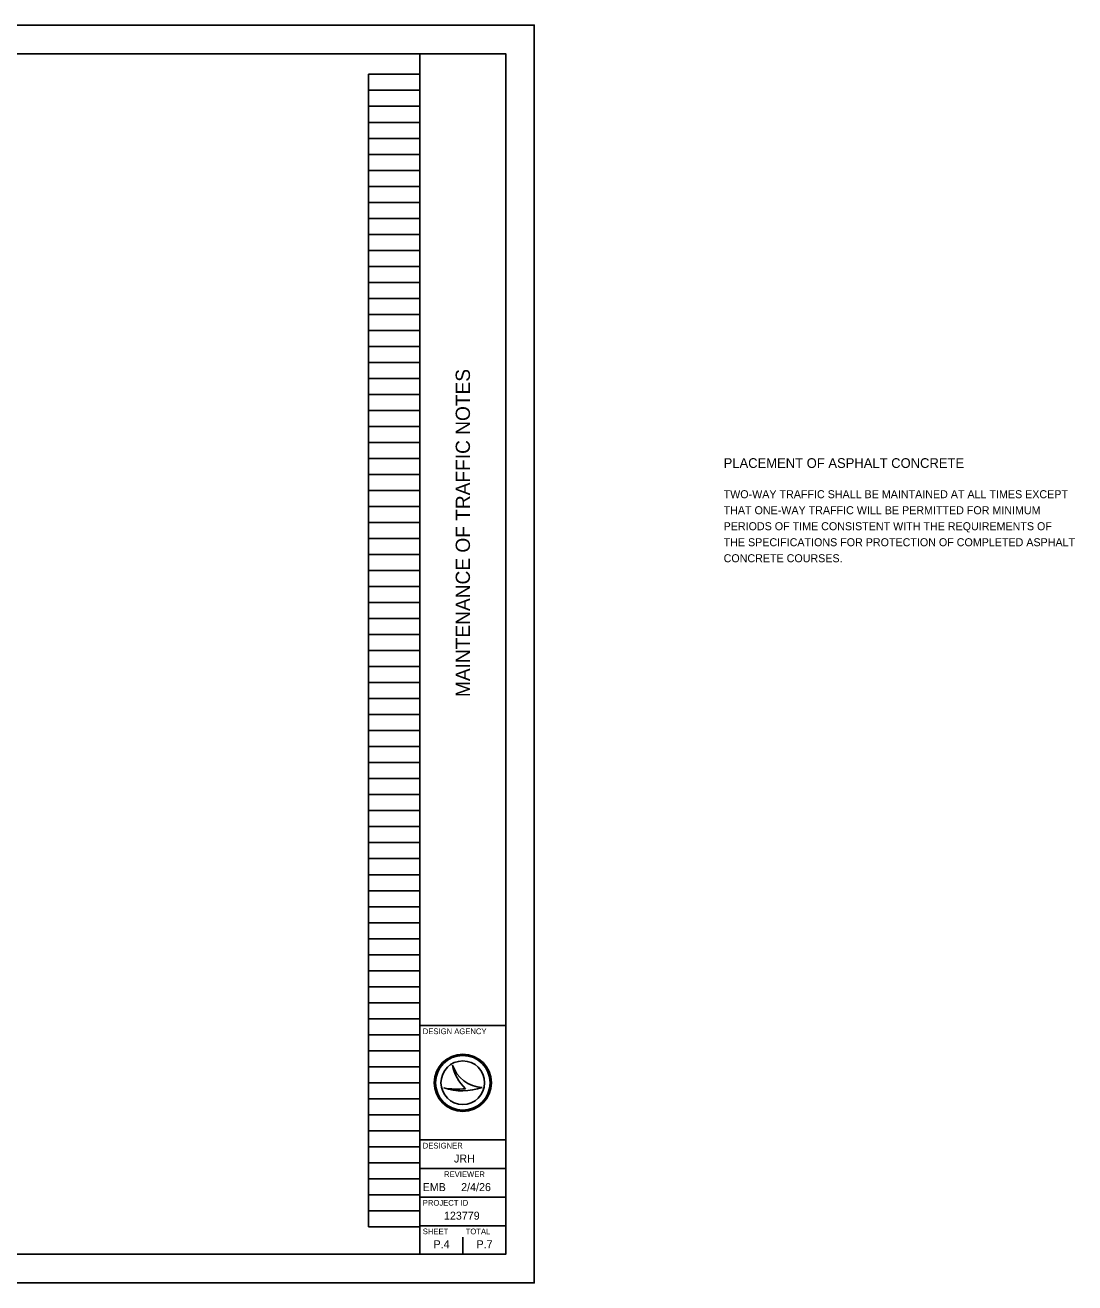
# Model space of a CAD drawing. Extents: x 0 to 43.5, y 0 to 22.
# Drawn here: x 25.09 to 43.46, y 0 to 22 of the extents above; entities that cross this region are included whole.
import ezdxf

# ---------------------------------------------------------------- set-up
doc = ezdxf.new("R2010")
doc.units = 0
for name, color, linetype in [('SH_Border', 7, 'Continuous'), ('SH_Cut_Line', 7, 'Continuous'), ('SH_Data', 7, 'Continuous'), ('SH_Text', 7, 'Continuous')]:
    doc.layers.add(name, color=color, linetype=linetype)

msp = doc.modelspace()

# ---------------------------------------------------------------- linework, layer by layer
at = {"layer": 'SH_Border'}
for p, q in [((32, 0.5), (32, 21.5)), ((32, 4.5), (33.5, 4.5)), ((32, 2.5), (33.5, 2.5)), ((32, 2), (33.5, 2)), ((32, 1.5), (33.5, 1.5)), ((32, 1), (33.5, 1))]:
    msp.add_line(p, q, dxfattribs=at)
msp.add_lwpolyline([(1.5, 21.5), (33.5, 21.5), (33.5, 0.5), (1.5, 0.5)], close=True, dxfattribs=at)
at = {"layer": 'SH_Cut_Line'}
msp.add_lwpolyline([(0, 0), (34, 0), (34, 22), (0, 22)], close=True, dxfattribs=at)
at = {"layer": 'SH_Data'}
for p, q in [((31.1, 0.98), (31.1, 21.14)), ((31.1, 21.14), (32, 21.14)), ((32, 0.98), (32, 21.14)), ((31.1, 20.86), (32, 20.86)), ((31.1, 20.58), (32, 20.58)), ((31.1, 20.3), (32, 20.3)), ((31.1, 20.02), (32, 20.02)), ((31.1, 19.74), (32, 19.74)), ((31.1, 19.46), (32, 19.46)), ((31.1, 19.18), (32, 19.18)), ((31.1, 18.9), (32, 18.9)), ((31.1, 18.62), (32, 18.62)), ((31.1, 18.34), (32, 18.34)), ((31.1, 18.06), (32, 18.06)), ((31.1, 17.78), (32, 17.78)), ((31.1, 17.5), (32, 17.5)), ((31.1, 17.22), (32, 17.22)), ((31.1, 16.94), (32, 16.94)), ((31.1, 16.66), (32, 16.66)), ((31.1, 16.38), (32, 16.38)), ((31.1, 16.1), (32, 16.1)), ((31.1, 15.82), (32, 15.82)), ((31.1, 15.54), (32, 15.54)), ((31.1, 15.26), (32, 15.26)), ((31.1, 14.98), (32, 14.98)), ((31.1, 14.7), (32, 14.7)), ((31.1, 14.42), (32, 14.42)), ((31.1, 14.14), (32, 14.14)), ((31.1, 13.86), (32, 13.86)), ((31.1, 13.58), (32, 13.58)), ((31.1, 13.3), (32, 13.3)), ((31.1, 13.02), (32, 13.02)), ((31.1, 12.74), (32, 12.74)), ((31.1, 12.46), (32, 12.46)), ((31.1, 12.18), (32, 12.18)), ((31.1, 11.9), (32, 11.9)), ((31.1, 11.62), (32, 11.62)), ((31.1, 11.34), (32, 11.34)), ((31.1, 11.06), (32, 11.06)), ((31.1, 10.78), (32, 10.78)), ((31.1, 10.5), (32, 10.5)), ((31.1, 10.22), (32, 10.22)), ((31.1, 9.94), (32, 9.94)), ((31.1, 9.66), (32, 9.66)), ((31.1, 9.38), (32, 9.38)), ((31.1, 9.1), (32, 9.1)), ((31.1, 8.82), (32, 8.82)), ((31.1, 8.54), (32, 8.54)), ((31.1, 8.26), (32, 8.26)), ((31.1, 7.98), (32, 7.98)), ((31.1, 7.7), (32, 7.7)), ((31.1, 7.42), (32, 7.42)), ((31.1, 7.14), (32, 7.14)), ((31.1, 6.86), (32, 6.86)), ((31.1, 6.58), (32, 6.58)), ((31.1, 6.3), (32, 6.3)), ((31.1, 6.02), (32, 6.02)), ((31.1, 5.74), (32, 5.74)), ((31.1, 5.46), (32, 5.46)), ((31.1, 5.18), (32, 5.18)), ((31.1, 4.9), (32, 4.9)), ((31.1, 4.62), (32, 4.62)), ((31.1, 4.34), (32, 4.34)), ((31.1, 4.06), (32, 4.06)), ((31.1, 3.78), (32, 3.78)), ((32.567, 3.81), (32.567, 3.81)), ((31.1, 3.5), (32, 3.5)), ((32.417, 3.41), (32.417, 3.41)), ((32.75, 3.5), (32.75, 3.5)), ((33.087, 3.419), (33.087, 3.419)), ((31.1, 3.22), (32, 3.22)), ((31.1, 2.94), (32, 2.94)), ((31.1, 2.66), (32, 2.66)), ((31.1, 2.38), (32, 2.38)), ((31.1, 2.1), (32, 2.1)), ((31.1, 1.82), (32, 1.82)), ((31.1, 1.54), (32, 1.54)), ((31.1, 1.26), (32, 1.26)), ((31.1, 0.98), (32, 0.98)), ((32.375, 0.675), (32.375, 0.675)), ((32.75, 0.5), (32.75, 0.8))]:
    msp.add_line(p, q, dxfattribs=at)
for radius in [0.5, 0.477, 0.477, 0.382]:
    msp.add_circle((32.75, 3.5), radius, dxfattribs=at)
for centre, radius, start, end in [((33.116, 3.998), 0.58, 198.9257, 198.9319), ((33.347, 3.97), 0.796, 191.6379, 191.6421), ((33.116, 3.998), 0.58, 198.9319, 267.1657), ((33.347, 3.97), 0.796, 191.6421, 226.0947), ((32.739, 4.37), 1.013, 251.4576, 290.0832), ((32.648, 4.654), 1.266, 259.4964, 259.4995), ((32.739, 4.37), 1.013, 251.4527, 251.4576), ((32.648, 4.654), 1.266, 259.4995, 276.6672)]:
    msp.add_arc(centre, radius, start, end, dxfattribs=at)

# ---------------------------------------------------------------- texts
msp.add_text('MAINTENANCE OF TRAFFIC NOTES', height=0.25, rotation=90, dxfattribs=at).set_placement((32.875, 10.247))
for s, height, p in [('DESIGN AGENCY', 0.1, (32.05, 4.35)), ('DESIGNER', 0.1, (32.05, 2.35)), ('JRH', 0.14, (32.595, 2.105)), ('REVIEWER', 0.1, (32.422, 1.85)), ('EMB', 0.14, (32.047, 1.605)), ('2/4/26', 0.14, (32.721, 1.605)), ('PROJECT ID', 0.1, (32.05, 1.35)), ('123779', 0.14, (32.42, 1.105)), ('SHEET', 0.1, (32.05, 0.85)), ('TOTAL', 0.1, (32.8, 0.85)), ('P.4', 0.14, (32.237, 0.605)), ('P.7', 0.14, (32.989, 0.605))]:
    msp.add_text(s, height=height, dxfattribs=at).set_placement(p)
at = {"layer": 'SH_Text'}
for s, height, p in [('PLACEMENT OF ASPHALT CONCRETE', 0.17, (37.312, 14.255)), ('TWO-WAY TRAFFIC SHALL BE MAINTAINED AT ALL TIMES EXCEPT', 0.14, (37.312, 13.725)), ('THAT ONE-WAY TRAFFIC WILL BE PERMITTED FOR MINIMUM', 0.14, (37.312, 13.445)), ('PERIODS OF TIME CONSISTENT WITH THE REQUIREMENTS OF', 0.14, (37.312, 13.165)), ('THE SPECIFICATIONS FOR PROTECTION OF COMPLETED ASPHALT', 0.14, (37.312, 12.885)), ('CONCRETE COURSES.', 0.14, (37.312, 12.605))]:
    msp.add_text(s, height=height, dxfattribs=at).set_placement(p)

doc.saveas('drawing.dxf')
